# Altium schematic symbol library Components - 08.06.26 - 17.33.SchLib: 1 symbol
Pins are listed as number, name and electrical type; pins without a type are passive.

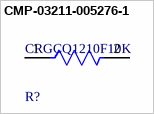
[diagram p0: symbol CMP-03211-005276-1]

## CMP-03211-005276-1
designator R?, comment CRGCQ1210F10K
CRGCQ1210 10KΩ 0.5W ±100ppm/°C 1% 200V; Manufacturer: TE Connectivity; Automotive Grade: Grade 913; Tolerance: 0.01
footprint FP-CRGCQ1210-IPC_A
footprint FP-CRGCQ1210-IPC_C
footprint FP-CRGCQ1210-IPC_B
pins: 1, 2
